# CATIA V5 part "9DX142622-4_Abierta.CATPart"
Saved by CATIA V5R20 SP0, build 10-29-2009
Part number: 9DX142622-4_Abierta
Revision: ANY
Definition: UNKNOWN
Nomenclature: 9DX142622-4_Abierta
Source: Unknown
Bounding box of the stored display mesh (mm): x -10.9 to 10.9, y -123.875 to -109.315, z -10.9 to 10.9
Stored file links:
  C:\Users\Utente\Desktop\IO LAVORO\3D X SITO CF\CUMSA\3D files DX\DX 142622\9DX142622-4_Abierta.CATPart
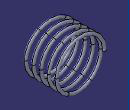
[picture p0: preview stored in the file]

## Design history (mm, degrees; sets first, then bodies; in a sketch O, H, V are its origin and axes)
Body1 "Revolución2" (main body)
  Solid1: solid without history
